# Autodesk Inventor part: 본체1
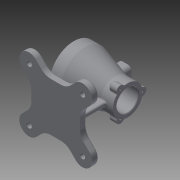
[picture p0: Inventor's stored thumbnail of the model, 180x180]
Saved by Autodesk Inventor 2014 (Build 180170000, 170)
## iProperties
Created: 2018-03
Part Number: 본체1
Material: Generic
Document SubType Name: Modeling
Designer: kb542
Density: 1 g/cm^3
Appearance: Default
Author: kb542
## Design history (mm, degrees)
sketch "스케치1"
  geometry: L1 (0, 0)-(100, 0); L2 (0, 35)-(0, 45); L3 (0, 45)-(20, 45); L4 (20, 45)-(77, 27.5); L5 (77, 27.5)-(100, 27.5); L6 (100, 27.5)-(100, 20); L7 (100, 20)-(73, 20); L8 (70, 23)-(70, 23); L9 (67, 26)-(26, 26); L10 (23, 29)-(23, 32); L11 (20, 35)-(0, 35); A1 r 3 centre (20, 32) between (23, 32) and (20, 35); A2 r 3 centre (26, 29) between (23, 29) and (26, 26); A3 r 3 centre (67, 23) between (70, 23) and (67, 26); A4 r 3 centre (73, 23) between (70, 23) and (73, 20); 4 further points
  constraints: 22 end point, 8 point on circle, 8 point on line, 8 tangent, 5 parallel, 4 centre point, 4 perpendicular, 3 equal radius, 2 vertical alignment, 1 horizontal
  dimensions: "d0" = 100 distance of L1.start L1.end; "d1" = 20 distance of L2.end L3.end; "d2" = 77 horizontal distance of L4.end L2.end; "d3" = 23 distance of point (23, 35) L2.start; "d4" = 30 distance of L6.end point (70, 20); "d5" = 47 distance of point (70, 26) point (23, 26) (derived); "d6" = 90 diameter of L3 L1; "d7" = 40 diameter of L7 L1; "d8" = 52 diameter of L9 L1; "d9" = 70 diameter of L11 L1; "d10" = 55 diameter of L5 L1; "d11" = 3 radius of A1
revolve "회전1" sketch "스케치1" stored, may be unused: angle "d12" = 90 deg
sketch "스케치2"
  geometry: C1 r 20 at (0, 0) reference; C2 r 7 at (0, 27.5); 2 further points
  constraints: 3 vertical alignment, 1 centre point, 1 coincident, 3 other
  dimensions: "d13" = 14 diameter of C2
extrude "돌출1" join sketch "스케치2" distance "d14" = 15; taper "d15" = 0 deg
hole "구멍1" diameter "d21" = 3.242; stored, may be unused: countersink angle "d25" = 90 deg, drill point angle "d27" = 118 deg; dims "d19" = 10, "d20" = 10, "d22" = 9, "d23" = 4, "d24" = 2, "d26" = 11
node "작업 평면1"
sketch "스케치3"
  geometry: L1 (-93.5, 45)-(-3.5, 45); L2 (-3.5, 45)-(-3.5, -45); L3 (-3.5, -45)-(-93.5, -45); L4 (-93.5, -45)-(-93.5, 45); L5 (-20, 45)-(-77, 27.5) reference; 5 further points
  constraints: 8 end point, 3 midpoint, 2 parallel, 2 vertical alignment, 1 horizontal, 1 horizontal alignment, 1 perpendicular
  dimensions: "d32" = 90 distance of L3.end L1.start; "d33" = 90 distance of L1.start L1.end
extrude "돌출2" join sketch "스케치3" distance "d34" = 12; taper "d35" = 0 deg
sketch "스케치4"
  geometry: L1 (93.5, -45)-(93.5, 45) reference; L2 (93.5, 45)-(3.5, 45) reference; L3 (3.5, 45)-(3.5, -45) reference; L4 (48.5, 0)-(-0.997, 49.497); L5 (-21.5, 0)-(48.5, 0); L6 (11.73, 62.225)-(28.956, 45); L7 (-13.725, 36.77)-(3.5, 19.544); L8 (48.5, 45)-(48.5, 0); L9 (110.725, 36.77)-(93.5, 19.544); L10 (83.739, 60.483)-(68.255, 45); A1 r 70 centre (48.5, 0) between (-0.997, 49.497) and (-21.5, 0); A2 r 18 centre (-0.997, 49.497) between (11.73, 62.225) and (-13.725, 36.77); A3 r 18 centre (97.997, 49.497) between (110.725, 36.77) and (83.739, 60.483); 2 further points
  constraints: 14 end point, 7 point on circle, 4 point on line, 3 centre point, 3 parallel, 3 perpendicular, 3 tangent, 2 midpoint, 1 coincident, 1 horizontal alignment, 1 symmetric about line, 1 vertical alignment, 1 other
  dimensions: "d36" = 140 diameter of A1; "d37" = 45 deg angle of L4 L5; "d38" = 36 diameter of A2
extrude "돌출3" join sketch "스케치4" distance "d39" = 12; taper "d40" = 0 deg
node "작업 평면2"
node "작업 평면3"
sketch "스케치5"
  geometry: L1 (-45, -82)-(-45, -70) reference; L2 (-45, -70)-(45, -70) reference; L3 (45, -70)-(45, -82) reference; L4 (45, -82)-(-45, -82) reference; L5 (0, 0)-(0, -70); L6 (-19.391, -17.32)-(-24, -70); L7 (19.391, -17.32)-(24, -70); C1 r 35.789 at (0, 0) reference; A1 r 26 centre (0, 0) between (-19.391, -17.32) and (19.391, -17.32) reference; A2 r 26 centre (0, 0) between (-19.391, -17.32) and (19.391, -17.32); 1 further point
  constraints: 6 end point, 4 point on circle, 2 point on line, 1 centre point, 1 concentric, 1 midpoint, 1 other
  dimensions: "d41" = 24 distance from line of L6.end L5; "d42" = 95 deg angle of L6 L2
extrude "돌출4" join sketch "스케치5" stored distance "d43" = 8; taper "d44" = 0 deg
sketch "스케치6"
  geometry: L1 (48.255, 37)-(-8.745, 54.5) reference; L2 (48.255, 127)-(68.255, 127) reference; L3 (68.255, 127)-(68.255, 117) reference; L4 (68.255, 117)-(48.255, 117) reference; L5 (45.255, 114)-(45.255, 111) reference; L6 (42.255, 108)-(1.255, 108) reference; L7 (-4.745, 102)-(-31.745, 102) reference; L8 (-31.745, 102)-(-31.745, 107.879) reference; L9 (-31.745, 107.879)-(-20.745, 107.879) reference; L10 (-20.745, 107.879)-(-19.771, 109.5) reference; L11 (-19.771, 109.5)-(-20.745, 111.121) reference; L12 (-20.745, 111.121)-(-31.745, 111.121) reference; L13 (-31.745, 111.121)-(-31.745, 116.5) reference; L14 (-31.745, 116.5)-(-16.745, 116.5) reference; L15 (-16.745, 116.5)-(-16.745, 109.5) reference; L16 (-16.745, 109.5)-(-8.745, 109.5) reference; L17 (-8.745, 109.5)-(48.255, 127) reference; L18 (68.255, 37)-(48.255, 37) reference; L19 (48.255, 37)-(22.255, 44.982) reference; L20 (22.255, 44.982)-(22.255, 12) reference; L21 (22.255, 12)-(64.755, 12) reference; L22 (64.755, 12)-(64.755, 0) reference; L23 (64.755, 0)-(-25.245, 0) reference; L24 (-25.245, 0)-(-25.245, 12) reference; L25 (-25.245, 12)-(14.255, 12) reference; L26 (14.255, 12)-(14.255, 47.439) reference; L27 (14.255, 47.439)-(-8.745, 54.5) reference; L28 (-8.745, 54.5)-(-31.745, 54.5) reference; L29 (-31.745, 54.5)-(-31.745, 62) reference; L30 (-31.745, 62)-(-4.745, 62) reference; L31 (1.255, 56)-(42.255, 56) reference; L32 (45.255, 53)-(45.255, 50) reference; L33 (48.255, 47)-(68.255, 47) reference; L34 (68.255, 47)-(68.255, 37) reference; L35 (-18.745, 44.982)-(-18.745, 15.773); L36 (55.255, 35.008)-(55.255, 19.155); A1 r 3 centre (48.255, 114) between (48.255, 117) and (45.255, 114) reference; A2 r 3 centre (42.255, 111) between (42.255, 108) and (45.255, 111) reference; A3 r 3 centre (1.255, 105) between (1.255, 108) and (-1.745, 105) reference; A4 r 3 centre (-4.745, 105) between (-4.745, 102) and (-1.745, 105) reference; A5 r 3 centre (-4.745, 59) between (-1.745, 59) and (-4.745, 62) reference; A6 r 3 centre (1.255, 59) between (-1.745, 59) and (1.255, 56) reference; A7 r 3 centre (42.255, 53) between (45.255, 53) and (42.255, 56) reference; A8 r 3 centre (48.255, 50) between (45.255, 50) and (48.255, 47) reference; 1 further point
  constraints: 4 end point, 1 parallel
  dimensions: "d103" = 13 distance between parallel lines of L29 L35; "d104" = 13 distance between parallel lines of L34 L36
  node "절단 모서리 투영2"
feature "리브1" dims "d47" = 1, "d48" = 8, "d49" = 0, "d50" = 0, "d51" = 1, "d52" = 1
feature "리브2" dims "d53" = 1, "d54" = 8, "d55" = 0, "d56" = 0, "d57" = 1, "d58" = 1
sketch "스케치7" dims "d59" = 80
  geometry: C1 r 45 at (0, 0) reference; C2 r 35 at (0, 0) reference; 2 further points
  constraints: 2 vertical alignment, 1 coincident, 2 other
hole "구멍2" sketch "스케치7" at (0, 40) diameter "d60" = 3.242; stored, may be unused: countersink angle "d64" = 90 deg, drill point angle "d66" = 118 deg; dims "d61" = 9, "d62" = 4, "d63" = 2, "d65" = 11
node "작업 평면4"
sketch "스케치9"
  geometry: L1 (-54.5, 12.5)-(-45.5, 12.5); L2 (-37.5, 4.5)-(-37.5, -4.5); L3 (-45.5, -12.5)-(-54.5, -12.5); L4 (-62.5, -4.5)-(-62.5, 4.5); L5 (-77, -4)-(-54, -4) reference; L6 (-54, -4)-(-54, -20.322) reference; L7 (-46, -20.568)-(-46, -4) reference; L8 (-46, -4)-(-20, -4) reference; L9 (-20, -4)-(-20, 4) reference; L10 (-20, 4)-(-46, 4) reference; L11 (-46, 4)-(-46, 20.568) reference; L12 (-54, 20.322)-(-54, 4) reference; L13 (-54, 4)-(-77, 4) reference; L14 (-77, -4)-(-77, 4) reference; L15 (-28.956, 45)-(-68.255, 45) reference; L16 (0, 45)-(0, -45) reference; A1 r 8 centre (-54.5, 4.5) between (-54.5, 12.5) and (-62.5, 4.5); A2 r 8 centre (-45.5, 4.5) between (-37.5, 4.5) and (-45.5, 12.5); A3 r 8 centre (-45.5, -4.5) between (-45.5, -12.5) and (-37.5, -4.5); A4 r 8 centre (-54.5, -4.5) between (-62.5, -4.5) and (-54.5, -12.5); 7 further points
  constraints: 8 end point, 8 point on circle, 8 tangent, 6 point on line, 4 centre point, 3 equal radius, 3 midpoint, 2 parallel, 1 horizontal, 1 horizontal alignment, 1 perpendicular, 2 other
  dimensions: "d71" = 25 distance of point (-62.5, 12.5) point (-37.5, 12.5); "d72" = 25 distance of point (-62.5, -12.5) point (-62.5, 12.5); "d73" = 37.5 distance between parallel lines of L16 L2; "d74" = 8 radius of A1
extrude "돌출5" join sketch "스케치9" stored distance "d75" = 0; taper "d76" = 0 deg
sketch "스케치10"
  geometry: L1 (45.5, 12.5)-(54.5, 12.5) reference; L2 (45.5, 7.5)-(54.5, 7.5); L3 (57.5, 4.5)-(57.5, -4.5); L4 (54.5, -7.5)-(45.5, -7.5); L5 (42.5, -4.5)-(42.5, 4.5); A1 r 3 centre (45.5, 4.5) between (45.5, 7.5) and (42.5, 4.5); A2 r 3 centre (54.5, 4.5) between (57.5, 4.5) and (54.5, 7.5); A3 r 3 centre (54.5, -4.5) between (54.5, -7.5) and (57.5, -4.5); A4 r 3 centre (45.5, -4.5) between (42.5, -4.5) and (45.5, -7.5); 7 further points
  constraints: 8 end point, 8 point on circle, 8 tangent, 6 point on line, 4 centre point, 3 equal radius, 3 midpoint, 2 parallel, 1 horizontal, 1 horizontal alignment, 1 perpendicular, 1 vertical alignment
  dimensions: "d77" = 15 distance of point (42.5, 7.5) point (57.5, 7.5); "d78" = 15 distance of point (42.5, -7.5) point (42.5, 7.5); "d79" = 3 radius of A1
extrude "돌출6" cut sketch "스케치10" distance "d80" = 30; taper "d81" = 0 deg
fillet "모깎기1" dims "d82" = 3, "d83" = 1
fillet "모깎기2" dims "d84" = 3
fillet "모깎기3" dims "d85" = 1
fillet "모깎기4" dims "d89" = 3
fillet "모깎기5" dims "d90" = 3
chamfer "모따기1" distance "d91" = 1; stored, may be unused: second distance "d92" = 2, angle "d93" = 45 deg
sketch "스케치11"
  geometry: C1 r 5 at (-0.997, 49.497); C2 r 5 at (97.997, 49.497); C3 r 5 at (97.997, -49.497); C4 r 5 at (-0.997, -49.497); A1 r 18 centre (-0.997, -49.497) between (-13.725, -36.77) and (11.73, -62.225) reference; A2 r 18 centre (97.997, -49.497) between (83.739, -60.483) and (110.725, -36.77) reference; A3 r 18 centre (97.997, 49.497) between (110.725, 36.77) and (83.739, 60.483) reference; A4 r 18 centre (-0.997, 49.497) between (11.73, 62.225) and (-13.725, 36.77) reference; 1 further point
  constraints: 4 centre point, 4 coincident, 3 equal radius
  dimensions: "d94" = 10 diameter of C1
extrude "돌출7" cut sketch "스케치11" distance "d95" = 30; taper "d96" = 0 deg
fillet "모깎기6" dims "d97" = 25
fillet "모깎기7" dims "d98" = 3
sketch "스케치12"
  geometry: L1 (10, 1)-(10, -1) reference; L2 (39.311, 42)-(57.9, 42) reference; L3 (57.9, -42)-(39.311, -42) reference; L4 (90.5, 9.189)-(90.5, -9.189) reference; L5 (10, 0)-(90.5, 0); L6 (48.606, 42)-(48.606, -42); L7 (3.5, 9.189)-(3.5, -9.189) reference; 2 further points
  constraints: 4 end point, 4 midpoint, 1 other
  dimensions: "d99" = 35 distance from line of L5 point (48.5, -35); "d100" = 45 distance from line of L7 point (48.5, -35)
feature "엠보싱1" sketch "스케치12" dims "d0" = 100, "d101" = 0.5, "d102" = 0
sketch "스케치13"
  geometry: L1 (77.699, 50.201)-(86.003, 58.505) reference; L2 (39.311, 42)-(57.9, 42) reference; L3 (9.609, 60.104)-(19.512, 50.201) reference; L4 (-1.701, 28.988)-(-11.604, 38.891) reference; L5 (6.5, -9.189)-(6.5, 9.189) reference; L6 (-11.604, -38.891)-(-1.701, -28.988) reference; L7 (19.512, -50.201)-(9.609, -60.104) reference; L8 (57.9, -42)-(39.311, -42) reference; L9 (86.003, -58.505)-(77.699, -50.201) reference; L10 (98.701, -28.988)-(108.604, -38.891) reference; L11 (90.5, 9.189)-(90.5, -9.189) reference; L12 (108.604, 38.891)-(98.701, 28.988) reference; L13 (84, 7)-(57, 7) reference; L14 (90, -1)-(90, 1) reference; L15 (57, -7)-(84, -7) reference; L16 (57, -20.726)-(57, -7) reference; L17 (49, -26.749)-(51, -26.749) reference; L18 (43, -7)-(43, -20.726) reference; L19 (16, -7)-(43, -7) reference; L20 (10, 1)-(10, -1) reference; L21 (43, 7)-(16, 7) reference; L22 (43, 20.726)-(43, 7) reference; L23 (51, 26.749)-(49, 26.749) reference; L24 (57, 7)-(57, 20.726) reference; L25 (60.511, -34.824)-(60.511, -35.871) reference; L26 (62.899, -35.708)-(62.937, -36.007) reference; L27 (60.153, -36.191)-(60.153, -33.288) reference; L28 (60.153, -33.288)-(62.47, -33.288) reference; L29 (62.47, -33.288)-(62.47, -33.586) reference; L30 (62.47, -33.586)-(60.511, -33.586) reference; L31 (60.511, -33.586)-(60.511, -34.525) reference; L32 (60.511, -34.525)-(62.258, -34.525) reference; L33 (62.258, -34.525)-(62.258, -34.824) reference; L34 (62.258, -34.824)-(60.511, -34.824) reference; L35 (58.459, -32.832)-(58.459, -36.332) reference; L36 (58.459, -36.332)-(58.096, -36.332) reference; L37 (58.096, -36.332)-(58.096, -32.664) reference; L38 (58.096, -32.664)-(58.383, -32.664) reference; L39 (57.531, -32.913)-(57.531, -36.132) reference; L40 (57.531, -36.132)-(57.168, -36.132) reference; L41 (57.168, -36.132)-(57.168, -34.194) reference; L42 (57.168, -34.194)-(56.343, -34.194) reference; L43 (56.343, -34.194)-(56.343, -33.917) reference; L44 (56.343, -33.917)-(57.168, -33.917) reference; L45 (57.168, -33.917)-(57.168, -32.723) reference; L46 (57.168, -32.723)-(57.466, -32.723) reference; L47 (58.573, -37.103)-(58.573, -37.402) reference; L48 (58.573, -37.402)-(55.116, -37.402) reference; L49 (55.116, -37.402)-(55.116, -35.871) reference; L50 (55.116, -35.871)-(55.382, -35.871) reference; L51 (55.474, -36.034)-(55.474, -37.103) reference; L52 (55.474, -37.103)-(58.573, -37.103) reference; L53 (56.831, -35.198)-(56.587, -35.475) reference; L54 (54.432, -35.638)-(54.182, -35.366) reference; L55 (55.436, -32.875)-(55.756, -32.875) reference; L56 (53.325, -35.784)-(53.683, -35.784) reference; L57 (53.651, -34.259)-(53.287, -34.259) reference; L58 (49.721, -33.092)-(49.721, -33.423) reference; L59 (49.721, -33.423)-(48.473, -33.423) reference; L60 (48.473, -33.423)-(48.473, -37.092) reference; L61 (48.473, -37.092)-(48.109, -37.092) reference; L62 (48.109, -37.092)-(48.109, -33.423) reference; L63 (48.109, -33.423)-(46.866, -33.423) reference; L64 (46.866, -33.423)-(46.866, -33.092) reference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; C1 r 5 at (97.997, -49.497) reference; C2 r 5 at (-0.997, 49.497) reference; C3 r 5 at (97.997, 49.497) reference; C4 r 5 at (-0.997, -49.497) reference; A1 r 28 centre (57.9, 70) between (57.9, 42) and (77.699, 50.201) reference; A2 r 28 centre (39.311, 70) between (19.512, 50.201) and (39.311, 42) reference; A3 r 15 centre (-0.997, 49.497) between (9.609, 60.104) and (-11.604, 38.891) reference; A4 r 28 centre (-21.5, 9.189) between (6.5, 9.189) and (-1.701, 28.988) reference; A5 r 28 centre (-21.5, -9.189) between (-1.701, -28.988) and (6.5, -9.189) reference; A6 r 15 centre (-0.997, -49.497) between (-11.604, -38.891) and (9.609, -60.104) reference; A7 r 28 centre (39.311, -70) between (39.311, -42) and (19.512, -50.201) reference; A8 r 28 centre (57.9, -70) between (77.699, -50.201) and (57.9, -42) reference; A9 r 15 centre (97.997, -49.497) between (86.003, -58.505) and (108.604, -38.891) reference; A10 r 28 centre (118.5, -9.189) between (90.5, -9.189) and (98.701, -28.988) reference; A11 r 28 centre (118.5, 9.189) between (98.701, 28.988) and (90.5, 9.189) reference; A12 r 15 centre (97.997, 49.497) between (108.604, 38.891) and (86.003, 58.505) reference; A13 r 6 centre (84, 1) between (90, 1) and (84, 7) reference; A14 r 6 centre (84, -1) between (84, -7) and (90, -1) reference; A15 r 6 centre (16, -1) between (10, -1) and (16, -7) reference; A16 r 6 centre (16, 1) between (16, 7) and (10, 1) reference; 58 further points; 4 other entities
  constraints: 72 other
node "솔리드1"
pattern_circular "원형 패턴1" dims angle "d17" = 360 deg
pattern_circular "원형 패턴2" dims angle "d29" = 360 deg
mirror "대칭1"
pattern_circular "원형 패턴3" dims angle "d68" = 360 deg
pattern_circular "원형 패턴4" dims angle "d87" = 360 deg
node "투영된 루프1"
node "절단 모서리 투영1"
other parameters: "d31" = -82, "d70" = 45
